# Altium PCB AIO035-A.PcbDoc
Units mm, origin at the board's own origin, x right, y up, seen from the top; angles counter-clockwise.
Board outline 100.5 x 55.66 mm, 2 copper layers (TopLayer, BottomLayer); 10 components, 10 nets, 49 pads, 92 vias.
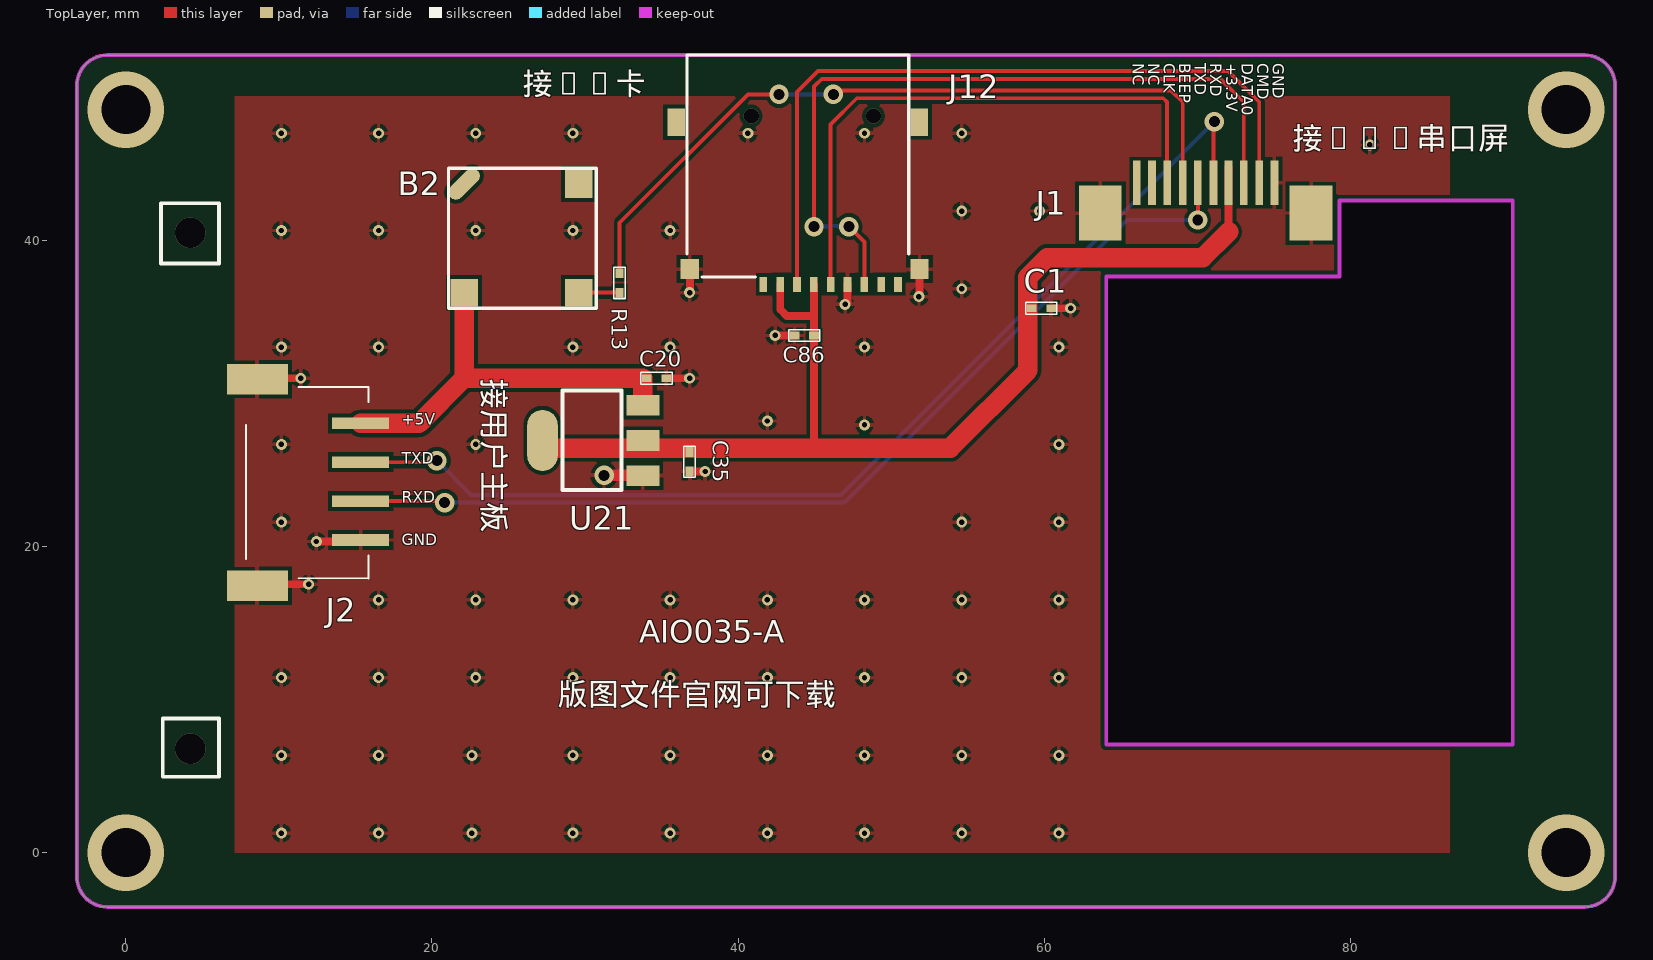
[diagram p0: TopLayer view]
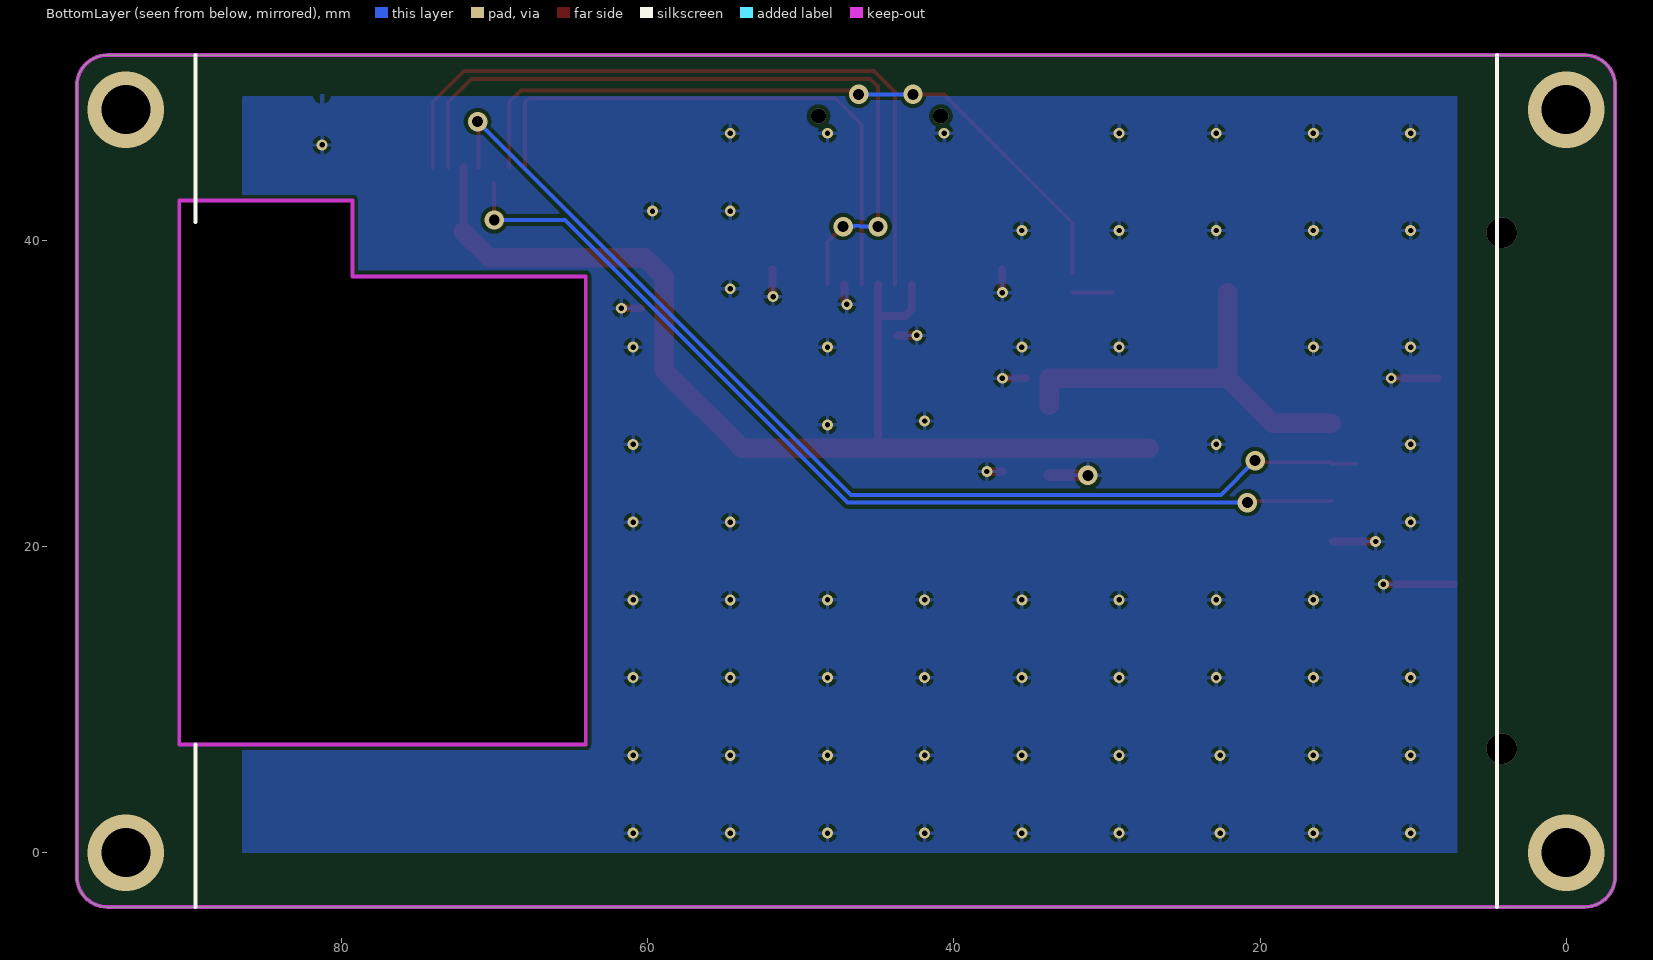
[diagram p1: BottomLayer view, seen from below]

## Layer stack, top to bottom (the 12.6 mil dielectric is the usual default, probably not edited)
TopLayer: signal copper 0.0356
Dielectric: dielectric 0.32, FR-4, Dk 4.8
BottomLayer: signal copper 0.0356

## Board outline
-3.2,-1.56 -3.2,50.1 cw(c-1.2,50.1) -1.2,52.1 95.3,52.1 cw(c95.3,50.1) 97.3,50.1 97.3,-1.56 cw(c95.3,-1.56) 95.3,-3.56 -1.2,-3.56 cw(c-1.2,-1.56)
cut-out: 64.05,7.068 90.612,7.067 90.612,42.6 79.3,42.6 79.3,37.64 71.675,37.64 64.05,37.64

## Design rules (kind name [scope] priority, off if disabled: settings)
Clearance [All] p1: gap=0.254
FabricationTestPointUsage TestPointUsage [All] p1: valid=0 allowmultiple=FALSE
FabricationTestpoint Testpoint [All] p1: side=3 testpointundercomponent=TRUE minsize=1.016 maxsize=2.54 preferedsize=1.524 minholesize=0.508 maxholesize=1.016 preferedholesize=0.813 testpointgrid=0.025 allowsidetop=TRUE allowsidebottom=TRUE usegrid=TRUE gridtolerance=0
HoleSize [All] p1: absolutevalues=TRUE maxlimit=7.62 minlimit=0.025 maxpercent=80.000 minpercent=20.000
PolygonConnect [All] p1: connectstyle=Relief reliefconductorwidth=0.254 reliefentries=4 polygonreliefangle="90 Angle"
RoutingVias [All] p1: holewidth=0.711 width=1.27 viastyle="Through Hole" minholewidth=0.711 minwidth=1.27 maxholewidth=0.711 maxwidth=1.27
SilkToSilkClearance [All] p1: silktosilkclearance=0
SilkscreenOverComponentPads [All] p1: minsilkscreentomaskgap=0
SolderMaskExpansion [All] p1: expansion=0.102
Width [All] p1: maxlimit=1.27 minlimit=0.152 preferedwidth=0.508 minimp=50.000000 maximp=50.000000 favimp=50.000000
23 further rules are at their usual default settings.

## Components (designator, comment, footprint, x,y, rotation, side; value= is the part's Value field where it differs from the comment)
B2 "KLJ-8530" BEEP 22.098,36.576 r0 top locked
C1 "4.7uF/6.3V" 0402A 59.182,35.56 r0 top
C20 "4.7uF/6.3V" 0402A 34.036,30.988 r0 top
C35 "4.7uF/6.3V" 0402A 36.83,26.162 r270 top
C86 "4.7uF/6.3V" 0402A 44.958,33.782 r180 top
J1 "FPC1.0-10下接" FPC1.0-10下接 66.05,43.76 r0 top locked
J2 "2.0-4" FPC2.54-4 15.34,20.42 r270 top locked
J12 "TF卡" TF卡 41.65,37.114 r180 top locked
R13 "62R" 0402A 32.258,36.576 r90 top
U21 "AMS1117-3.3" AMS1117-3.3 33.782,26.924 r90 top locked

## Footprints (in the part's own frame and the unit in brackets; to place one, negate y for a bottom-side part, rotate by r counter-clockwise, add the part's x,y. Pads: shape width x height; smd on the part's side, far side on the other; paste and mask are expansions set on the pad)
0402A [mil]
  rect 25x20 smd: 1(0,0) 2(50,0)
  silkscreen extent -15,-15 65,15
AMS1117-3.3 [mm]
  rect 1.35x2.15 smd: 1(-2.3,0) 2(0,0) 3(2.3,0)
  oval 4x2 smd: 4(0,6.56)
  silkscreen extent -3.25,1.4 3.25,5.25
BEEP [mm]
  rect 1.8x1.8 smd: 1(0,0) 2(7.5,0) 3(7.5,7.1)
  oval 2.5x1 smd rot 45: 4(0,7.1)
  silkscreen extent -1.02,-1.02 8.64,8.13
FPC1.0-10下接 [mil]
  rect 20x114 smd: 1(0,0) 2(39,0) 3(78,0) 4(118,0) 5(157,0) 6(197,0) 7(236,0) 8(275,0) 9(315,0) 10(354,0)
  rect 110x142 smd: 11(-94,-78) 12(448,-78)
FPC2.54-4 [mil]
  rect 30x147 smd: 1(0,0) 2(-100,0) 3(-200,0) 4(-300,0)
  rect 78x157 smd: 5(118.11,-265.75) 6(-413.39,-265.75)
  silkscreen extent -394,-295 99,20
TF卡 [mm]
  rect 0.5x1 smd: 1(0,0) 2(-1.1,0) 3(-2.2,0) 4(-3.3,0) 5(-4.4,0) 6(-5.5,0) 7(-6.6,0) 8(-7.7,0) 9(-8.8,0)
  rect 1.2x1.3 smd: 10(4.8,-1) 11(-10.2,-1)
  rect 1.143x1.778 smd: 12(5.7,-10.6) 13(-10.2,-10.6)
  silkscreen extent -9.5,-15 5,-0.5

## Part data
B2: library part BEEP
C1 C20 C35 C86: library part C
J12: library part TF?
R13: library part RES1

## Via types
v1: diameter 0.711, hole 0.356, TopLayer to BottomLayer, 75 vias
v2: diameter 1.27, hole 0.711, TopLayer to BottomLayer, 9 vias
v3: diameter 5, hole 3.2, TopLayer to BottomLayer, 4 vias
v4: diameter 1, hole 1, TopLayer to BottomLayer, 2 vias
v5: diameter 2, hole 2, TopLayer to BottomLayer, 2 vias

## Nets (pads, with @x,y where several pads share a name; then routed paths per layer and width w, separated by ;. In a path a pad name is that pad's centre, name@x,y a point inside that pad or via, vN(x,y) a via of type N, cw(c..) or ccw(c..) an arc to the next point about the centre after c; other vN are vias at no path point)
3.3V: C1.1 C35.1 C86.1 J1.7 J12.2 J12.4 U21.2 U21.4 | length 73.2
  TopLayer w0.508: J12.2 42.75,35.482 43.18,35.052 44.958,35.052 ; J12.4 44.958,37.106 44.958,35.052 ; 44.958,26.416 C86.1 44.958,35.052 ; 72.044,40.548 J1.7@72.044,44.76
  TopLayer w1.27: U21.4@27.222,26.416 44.958,26.416 53.848,26.416 58.928,31.496 58.928,37.592 60.198,38.862 70.358,38.862 72.044,40.548
5V: B2.1 C20.1 J2.4 U21.3 | length 26.8
  TopLayer w1.27: J2.4 19.15,28.04 22.098,30.988 ; B2.1 22.098,30.988 ; U21.3 C20.1@33.782,30.734 ; C20.1@33.782,30.988 22.098,30.988
BEEP: J1.4 R13.2 | length 48.1
  TopLayer w0.254: R13.2 32.258,41.148 40.64,49.53 v2(42.672,49.53) ; v2@46.482,49.53 46.482,49.784 68.285,49.784 69.047,49.022 J1.4@69.047,44.76
  BottomLayer w0.254: v2(42.672,49.53) v2(46.228,49.53)
CLK: J1.3 J12.5 | length 37.5
  TopLayer w0.254: J12.5 46.05,47.574 47.752,49.276 67.777,49.276 68.031,49.022 J1.3@68.031,44.76
CMD: J1.9 J12.3 | length 48.4
  TopLayer w0.254: J12.3 43.85,49.692 45.212,51.054 72.019,51.054 74.051,49.022 J1.9@74.051,44.76
DAT0: J1.8 J12.7 | length 49
  TopLayer w0.254: v2@44.704,40.894 44.958,41.148 44.958,50.038 45.466,50.546 71.511,50.546 73.035,49.022 J1.8@73.035,44.76 ; v2@47.752,40.894 47.498,40.64 48.25,39.888 J12.7
  BottomLayer w0.254: v2(44.958,40.894) 46.105,40.894 46.157,40.947 46.473,40.947 46.526,40.894 v2(47.244,40.894)
GND: C1.2 C20.2 C35.2 C86.2 J1.10 J1.11 J1.12 J2.1 J2.5 J2.6 J12.6 J12.10 J12.11 U21.1 | length 22.4
  TopLayer w0.508: J2.5@7.364,17.526 v1(11.938,17.526) ; J2.6@8.41,30.988 v1(11.43,30.988) ; v1(12.446,20.32) J2.1@15.24,20.32 ; C20.2 v1(36.83,30.988) ; C35.2 v1(37.846,24.892) ; v1@36.85,36.596 J12.10 ; v1(42.418,33.782) C86.2 ; v1@47.15,35.974 J12.6 ; v1@51.85,36.356 J12.11 ; C1.2 v1(61.722,35.56)
  TopLayer w0.762: v2(31.242,24.638) U21.1@33.768,24.638
  other v1: 10.16,1.27 16.51,1.27 22.606,1.27 29.21,1.27 35.56,1.27 41.91,1.27 48.26,1.27 54.61,1.27 60.96,1.27 10.16,6.35 16.51,6.35 22.606,6.35 29.21,6.35 35.56,6.35 41.91,6.35 48.26,6.35 54.61,6.35 60.96,6.35 10.16,11.43 16.51,11.43 22.86,11.43 29.21,11.43 35.56,11.43 41.91,11.43 48.26,11.43 54.61,11.43 60.96,11.43 16.51,16.51 22.86,16.51 29.21,16.51 35.56,16.51 41.91,16.51 48.26,16.51 54.61,16.51 60.96,16.51 10.16,21.59 54.61,21.59 60.96,21.59 10.16,26.67 22.86,26.67 60.96,26.67 48.26,27.94 41.91,28.194 10.16,33.02 16.51,33.02 29.21,33.02 35.56,33.02 48.26,33.02 60.96,33.02 46.99,35.814 51.816,36.322 36.83,36.576 54.61,36.83 10.16,40.64 16.51,40.64 22.86,40.64 29.21,40.64 35.56,40.64 54.61,41.91 59.69,41.91 81.28,46.228 10.16,46.99 16.51,46.99 22.86,46.99 29.21,46.99 40.64,46.99 48.26,46.99 54.61,46.99
NetB2_2: B2.2 R13.1 | length 2.7
  TopLayer w0.254: B2.2 R13.1
RXD: J1.5 J2.2 | length 64.8
  TopLayer w0.254: J2.2 20.728,22.96 v2(20.828,22.86) ; v2(70.028,41.326) 70.038,41.336 J1.5
  BottomLayer w0.254: v2(20.828,22.86) 46.946,22.86 65.387,41.3 ; 65.412,41.326 v2(70.028,41.326) v2@70.002,41.3
TXD: J1.6 J2.3 | length 71.6
  TopLayer w0.254: J2.3@13.716,25.4 J2.3@15.342,25.4 ; J2.3 20.42,25.5 v2(20.32,25.6) ; J1.6@71.054,44.76 v2@71.054,47.686
  BottomLayer w0.254: v2(20.32,25.6) 22.552,23.368 46.736,23.368 v2(71.12,47.752)
pads on no net: B2.3 B2.4 J1.1 J1.2 J12.1 J12.8 J12.9 J12.12 J12.13
copper on no net:
  other v3: 0,0 94.1,0 0,48.54 94.1,48.54
  other v4: 40.85,48.114 48.85,48.114
  other v5: 4.21,6.78 4.21,40.48

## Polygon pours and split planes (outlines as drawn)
GND on BottomLayer "TopLayer-No Net" (solid, remove dead copper, pour order 4): 7.112,49.403 86.614,49.403 86.487,49.276 86.487,0 7.112,0
GND on TopLayer "TopLayer-No Net" (solid, remove dead copper, pour order 6): 7.112,49.403 7.112,0 86.487,0 86.487,49.403

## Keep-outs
KeepOutLayer:
  lines w0.254: -3.2,-1.56 ccw(c-1.2,-1.56) -1.2,-3.56 95.3,-3.56 ccw(c95.3,-1.56) 97.3,-1.56 97.3,50.1 ccw(c95.3,50.1) 95.3,52.1 -1.2,52.1 ccw(c-1.2,50.1) -3.2,50.1 -3.2,-1.56 ; 64.05,7.067 64.05,37.64 79.3,37.64 79.3,42.6 90.613,42.6 90.613,7.067 64.05,7.067

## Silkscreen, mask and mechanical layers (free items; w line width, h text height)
TopOverlay:
  lines w0.254: 2.286,38.481 6.096,38.481 6.096,42.418 2.286,42.418 2.286,38.481 ; 2.413,4.953 2.413,8.763 6.096,8.763 6.096,4.953 2.413,4.953
  text "NC" at 65.532,51.561 h1.27 r270
  text "NC" at 66.548,51.561 h1.27 r270
  text "CLK" at 67.564,51.562 h1.27 r270
  text "BEEP" at 68.569,51.562 h1.27 r270
  text "TXD" at 69.585,51.562 h1.27 r270
  text "RXD" at 70.601,51.561 h1.27 r270
  text "+3.3V" at 71.633,51.562 h1.27 r270
  text "DATA0" at 72.644,51.562 h1.27 r270
  text "CMD" at 73.66,51.562 h1.27 r270
  text "GND" at 74.676,51.562 h1.27 r270
  text "接TF卡" at 25.908,49.022 h2.54
  text "接AIO串口屏" at 76.2,45.466 h2.54
  text "接用户主板" at 22.86,30.988 h2.54 r270
  text "+5V" at 18.034,27.686 h1.27
  text "TXD" at 18.034,25.146 h1.27
  text "RXD" at 18.034,22.606 h1.27
  text "GND" at 18.034,19.812 h1.27
  text "AIO035-A" at 33.528,13.208 h2.54
  text "版图文件官网可下载" at 28.194,9.144 h2.54
BottomOverlay:
  lines w0.254: 4.51,-3.56 4.51,52.1 ; 89.55,-3.56 89.55,7.067 ; 89.55,41.2 89.55,52.1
